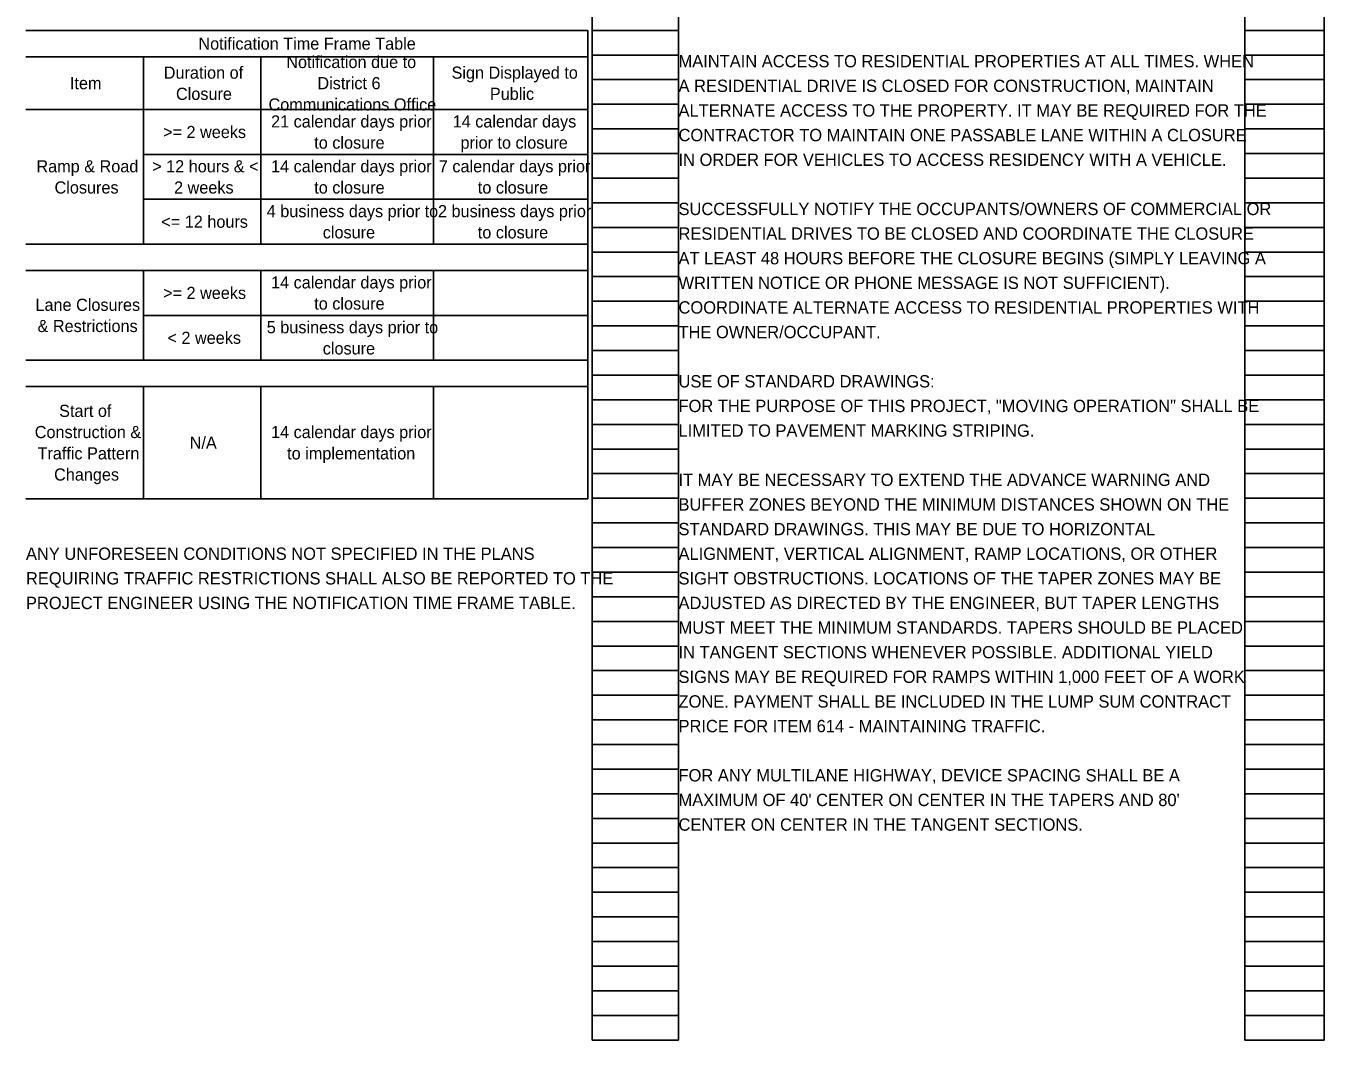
# Model space of a CAD drawing. Extents: x 37613.4 to 37668.4, y 18853.7 to 18946.8.
# Drawn here: x 37653.64 to 37668.4, y 18926.59 to 18938.13 of the extents above; entities that cross this region are included whole.
import ezdxf

# ---------------------------------------------------------------- set-up
doc = ezdxf.new("R2010")
doc.units = 0
for name, color, linetype in [('AP_P_Airside', 7, 'Continuous'), ('Default', 7, 'Continuous'), ('SH_Data', 7, 'Continuous'), ('SH_Text', 7, 'Continuous')]:
    doc.layers.add(name, color=color, linetype=linetype)

msp = doc.modelspace()

# ---------------------------------------------------------------- linework, layer by layer
at = {"layer": 'AP_P_Airside'}
for p, q in [((37653.641, 18938.075), (37660.031, 18938.075)), ((37660.031, 18938.075), (37660.031, 18932.75)), ((37653.641, 18937.775), (37660.031, 18937.775)), ((37654.976, 18937.775), (37654.976, 18935.645)), ((37656.311, 18937.775), (37656.311, 18935.645)), ((37658.276, 18937.775), (37658.276, 18935.645)), ((37653.641, 18937.175), (37660.031, 18937.175)), ((37654.976, 18936.665), (37660.031, 18936.665)), ((37654.976, 18936.155), (37660.031, 18936.155)), ((37653.641, 18935.645), (37660.031, 18935.645)), ((37653.641, 18935.345), (37660.031, 18935.345)), ((37654.976, 18935.345), (37654.976, 18934.325)), ((37656.311, 18935.345), (37656.311, 18934.325)), ((37658.276, 18935.345), (37658.276, 18934.325)), ((37654.976, 18934.835), (37660.031, 18934.835)), ((37653.641, 18934.325), (37660.031, 18934.325)), ((37653.641, 18934.025), (37660.031, 18934.025)), ((37654.976, 18934.025), (37654.976, 18932.75)), ((37656.311, 18934.025), (37656.311, 18932.75)), ((37658.276, 18934.025), (37658.276, 18932.75)), ((37653.641, 18932.75), (37660.031, 18932.75))]:
    msp.add_line(p, q, dxfattribs=at)
at = {"layer": 'SH_Data'}
for p, q in [((37660.081, 18926.595), (37660.081, 18946.755)), ((37661.061, 18926.595), (37661.061, 18946.755)), ((37667.501, 18926.595), (37667.501, 18946.755)), ((37668.401, 18926.595), (37668.401, 18946.755)), ((37660.081, 18938.075), (37661.061, 18938.075)), ((37667.501, 18938.075), (37668.401, 18938.075)), ((37660.081, 18937.795), (37661.061, 18937.795)), ((37667.501, 18937.795), (37668.401, 18937.795)), ((37660.081, 18937.515), (37661.061, 18937.515)), ((37667.501, 18937.515), (37668.401, 18937.515)), ((37660.081, 18937.235), (37661.061, 18937.235)), ((37667.501, 18937.235), (37668.401, 18937.235)), ((37660.081, 18936.955), (37661.061, 18936.955)), ((37667.501, 18936.955), (37668.401, 18936.955)), ((37660.081, 18936.675), (37661.061, 18936.675)), ((37667.501, 18936.675), (37668.401, 18936.675)), ((37660.081, 18936.395), (37661.061, 18936.395)), ((37667.501, 18936.395), (37668.401, 18936.395)), ((37660.081, 18936.115), (37661.061, 18936.115)), ((37667.501, 18936.115), (37668.401, 18936.115)), ((37660.081, 18935.835), (37661.061, 18935.835)), ((37667.501, 18935.835), (37668.401, 18935.835)), ((37660.081, 18935.555), (37661.061, 18935.555)), ((37667.501, 18935.555), (37668.401, 18935.555)), ((37660.081, 18935.275), (37661.061, 18935.275)), ((37667.501, 18935.275), (37668.401, 18935.275)), ((37660.081, 18934.995), (37661.061, 18934.995)), ((37667.501, 18934.995), (37668.401, 18934.995)), ((37660.081, 18934.715), (37661.061, 18934.715)), ((37667.501, 18934.715), (37668.401, 18934.715)), ((37660.081, 18934.435), (37661.061, 18934.435)), ((37667.501, 18934.435), (37668.401, 18934.435)), ((37660.081, 18934.155), (37661.061, 18934.155)), ((37667.501, 18934.155), (37668.401, 18934.155)), ((37660.081, 18933.875), (37661.061, 18933.875)), ((37667.501, 18933.875), (37668.401, 18933.875)), ((37660.081, 18933.595), (37661.061, 18933.595)), ((37667.501, 18933.595), (37668.401, 18933.595)), ((37660.081, 18933.315), (37661.061, 18933.315)), ((37667.501, 18933.315), (37668.401, 18933.315)), ((37660.081, 18933.035), (37661.061, 18933.035)), ((37667.501, 18933.035), (37668.401, 18933.035)), ((37660.081, 18932.755), (37661.061, 18932.755)), ((37667.501, 18932.755), (37668.401, 18932.755)), ((37660.081, 18932.475), (37661.061, 18932.475)), ((37667.501, 18932.475), (37668.401, 18932.475)), ((37660.081, 18932.195), (37661.061, 18932.195)), ((37667.501, 18932.195), (37668.401, 18932.195)), ((37660.081, 18931.915), (37661.061, 18931.915)), ((37667.501, 18931.915), (37668.401, 18931.915)), ((37660.081, 18931.635), (37661.061, 18931.635)), ((37667.501, 18931.635), (37668.401, 18931.635)), ((37660.081, 18931.355), (37661.061, 18931.355)), ((37667.501, 18931.355), (37668.401, 18931.355)), ((37660.081, 18931.075), (37661.061, 18931.075)), ((37667.501, 18931.075), (37668.401, 18931.075)), ((37660.081, 18930.795), (37661.061, 18930.795)), ((37667.501, 18930.795), (37668.401, 18930.795)), ((37660.081, 18930.515), (37661.061, 18930.515)), ((37667.501, 18930.515), (37668.401, 18930.515)), ((37660.081, 18930.235), (37661.061, 18930.235)), ((37667.501, 18930.235), (37668.401, 18930.235)), ((37660.081, 18929.955), (37661.061, 18929.955)), ((37667.501, 18929.955), (37668.401, 18929.955)), ((37660.081, 18929.675), (37661.061, 18929.675)), ((37667.501, 18929.675), (37668.401, 18929.675)), ((37660.081, 18929.395), (37661.061, 18929.395)), ((37667.501, 18929.395), (37668.401, 18929.395)), ((37660.081, 18929.115), (37661.061, 18929.115)), ((37667.501, 18929.115), (37668.401, 18929.115)), ((37660.081, 18928.835), (37661.061, 18928.835)), ((37667.501, 18928.835), (37668.401, 18928.835)), ((37660.081, 18928.555), (37661.061, 18928.555)), ((37667.501, 18928.555), (37668.401, 18928.555)), ((37660.081, 18928.275), (37661.061, 18928.275)), ((37667.501, 18928.275), (37668.401, 18928.275)), ((37660.081, 18927.995), (37661.061, 18927.995)), ((37667.501, 18927.995), (37668.401, 18927.995)), ((37660.081, 18927.715), (37661.061, 18927.715)), ((37667.501, 18927.715), (37668.401, 18927.715)), ((37660.081, 18927.435), (37661.061, 18927.435)), ((37667.501, 18927.435), (37668.401, 18927.435)), ((37660.081, 18927.155), (37661.061, 18927.155)), ((37667.501, 18927.155), (37668.401, 18927.155)), ((37660.081, 18926.875), (37661.061, 18926.875)), ((37667.501, 18926.875), (37668.401, 18926.875)), ((37660.081, 18926.595), (37661.061, 18926.595)), ((37667.501, 18926.595), (37668.401, 18926.595))]:
    msp.add_line(p, q, dxfattribs=at)

# ---------------------------------------------------------------- texts
at = {"layer": 'AP_P_Airside'}
for s, p in [('Notification Time Frame Table', (37655.602, 18937.856)), ('Notification due to ', (37656.601, 18937.647)), ('Duration of ', (37655.208, 18937.526)), ('Sign Displayed to ', (37658.48, 18937.526)), ('Item', (37654.141, 18937.406)), ('District 6 ', (37656.955, 18937.406)), ('Closure', (37655.347, 18937.285)), ('Communications Office', (37656.399, 18937.164)), ('Public', (37658.916, 18937.285)), ('>= 2 weeks', (37655.2, 18936.851)), ('21 calendar days prior ', (37656.428, 18936.971)), ('14 calendar days ', (37658.493, 18936.971)), ('to closure', (37656.919, 18936.73)), ('prior to closure', (37658.582, 18936.73)), ('Ramp & Road ', (37653.76, 18936.461)), ('> 12 hours & < ', (37655.076, 18936.461)), ('14 calendar days prior ', (37656.428, 18936.461)), ('7 calendar days prior ', (37658.336, 18936.461)), ('Closures', (37653.966, 18936.22)), ('2 weeks', (37655.325, 18936.22)), ('to closure', (37656.919, 18936.22)), ('to closure', (37658.779, 18936.22)), ('<= 12 hours', (37655.18, 18935.831)), ('4 business days prior to ', (37656.379, 18935.951)), ('2 business days prior ', (37658.326, 18935.951)), ('closure', (37657.016, 18935.71)), ('to closure', (37658.779, 18935.71)), ('14 calendar days prior ', (37656.428, 18935.141)), ('>= 2 weeks', (37655.2, 18935.021)), ('Lane Closures ', (37653.749, 18934.886)), ('to closure', (37656.919, 18934.9)), ('& Restrictions', (37653.773, 18934.645)), ('< 2 weeks', (37655.25, 18934.511)), ('5 business days prior to ', (37656.379, 18934.631)), ('closure', (37657.016, 18934.39)), ('Start of ', (37654.018, 18933.68)), ('Construction & ', (37653.741, 18933.439)), ('N/A', (37655.503, 18933.318)), ('14 calendar days prior ', (37656.428, 18933.439)), ('Traffic Pattern ', (37653.772, 18933.197)), ('to implementation', (37656.611, 18933.197)), ('Changes', (37653.961, 18932.956))]:
    msp.add_text(s, height=0.138, dxfattribs=at).set_placement(p)
at = {"layer": 'Default'}
for s, p in [('MAINTAIN ACCESS TO RESIDENTIAL PROPERTIES AT ALL TIMES. WHEN ', (37661.061, 18937.655)), ('A RESIDENTIAL DRIVE IS CLOSED FOR CONSTRUCTION, MAINTAIN ', (37661.061, 18937.375)), ('ALTERNATE ACCESS TO THE PROPERTY. IT MAY BE REQUIRED FOR THE ', (37661.061, 18937.095)), ('CONTRACTOR TO MAINTAIN ONE PASSABLE LANE WITHIN A CLOSURE ', (37661.061, 18936.815)), ('IN ORDER FOR VEHICLES TO ACCESS RESIDENCY WITH A VEHICLE.', (37661.061, 18936.535)), ('SUCCESSFULLY NOTIFY THE OCCUPANTS/OWNERS OF COMMERCIAL OR ', (37661.061, 18935.975)), ('RESIDENTIAL DRIVES TO BE CLOSED AND COORDINATE THE CLOSURE ', (37661.061, 18935.695)), ('AT LEAST 48 HOURS BEFORE THE CLOSURE BEGINS (SIMPLY LEAVING A ', (37661.061, 18935.415)), ('WRITTEN NOTICE OR PHONE MESSAGE IS NOT SUFFICIENT). ', (37661.061, 18935.135)), ('COORDINATE ALTERNATE ACCESS TO RESIDENTIAL PROPERTIES WITH ', (37661.061, 18934.855)), ('THE OWNER/OCCUPANT.', (37661.061, 18934.575))]:
    msp.add_text(s, height=0.14, dxfattribs=at).set_placement(p)
at = {"layer": 'SH_Text'}
for s, p in [('USE OF STANDARD DRAWINGS:', (37661.061, 18934.015)), ('FOR THE PURPOSE OF THIS PROJECT, "MOVING OPERATION" SHALL BE ', (37661.061, 18933.735)), ('LIMITED TO PAVEMENT MARKING STRIPING.', (37661.061, 18933.455)), ('IT MAY BE NECESSARY TO EXTEND THE ADVANCE WARNING AND ', (37661.061, 18932.895)), ('BUFFER ZONES BEYOND THE MINIMUM DISTANCES SHOWN ON THE ', (37661.061, 18932.615)), ('STANDARD DRAWINGS. THIS MAY BE DUE TO HORIZONTAL ', (37661.061, 18932.335)), ('ANY UNFORESEEN CONDITIONS NOT SPECIFIED IN THE PLANS ', (37653.641, 18932.055)), ('ALIGNMENT, VERTICAL ALIGNMENT, RAMP LOCATIONS, OR OTHER ', (37661.061, 18932.055)), ('REQUIRING TRAFFIC RESTRICTIONS SHALL ALSO BE REPORTED TO THE ', (37653.641, 18931.775)), ('SIGHT OBSTRUCTIONS. LOCATIONS OF THE TAPER ZONES MAY BE ', (37661.061, 18931.775)), ('PROJECT ENGINEER USING THE NOTIFICATION TIME FRAME TABLE.', (37653.641, 18931.495)), ('ADJUSTED AS DIRECTED BY THE ENGINEER, BUT TAPER LENGTHS ', (37661.061, 18931.495)), ('MUST MEET THE MINIMUM STANDARDS. TAPERS SHOULD BE PLACED ', (37661.061, 18931.215)), ('IN TANGENT SECTIONS WHENEVER POSSIBLE. ADDITIONAL YIELD ', (37661.061, 18930.935)), ('SIGNS MAY BE REQUIRED FOR RAMPS WITHIN 1,000 FEET OF A WORK ', (37661.061, 18930.655)), ('ZONE. PAYMENT SHALL BE INCLUDED IN THE LUMP SUM CONTRACT ', (37661.061, 18930.375)), ('PRICE FOR ITEM 614 - MAINTAINING TRAFFIC.', (37661.061, 18930.095)), ('FOR ANY MULTILANE HIGHWAY, DEVICE SPACING SHALL BE A ', (37661.061, 18929.535)), ("MAXIMUM OF 40' CENTER ON CENTER IN THE TAPERS AND 80' ", (37661.061, 18929.255)), ('CENTER ON CENTER IN THE TANGENT SECTIONS.', (37661.061, 18928.975))]:
    msp.add_text(s, height=0.14, dxfattribs=at).set_placement(p)

doc.saveas('drawing.dxf')
